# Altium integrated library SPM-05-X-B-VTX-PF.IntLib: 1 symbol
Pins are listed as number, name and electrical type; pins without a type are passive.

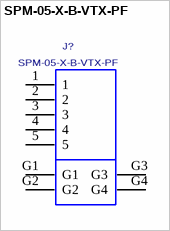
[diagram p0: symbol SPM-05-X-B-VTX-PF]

## SPM-05-X-B-VTX-PF
designator J?
SEALED PORT VERTICAL MINI USB.; MANUDACTURER: SAMTEC
footprint SPM-05-X-B-VTX-PF
pins: 1, 2, 3, 4, 5, G1, G2, G3, G4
